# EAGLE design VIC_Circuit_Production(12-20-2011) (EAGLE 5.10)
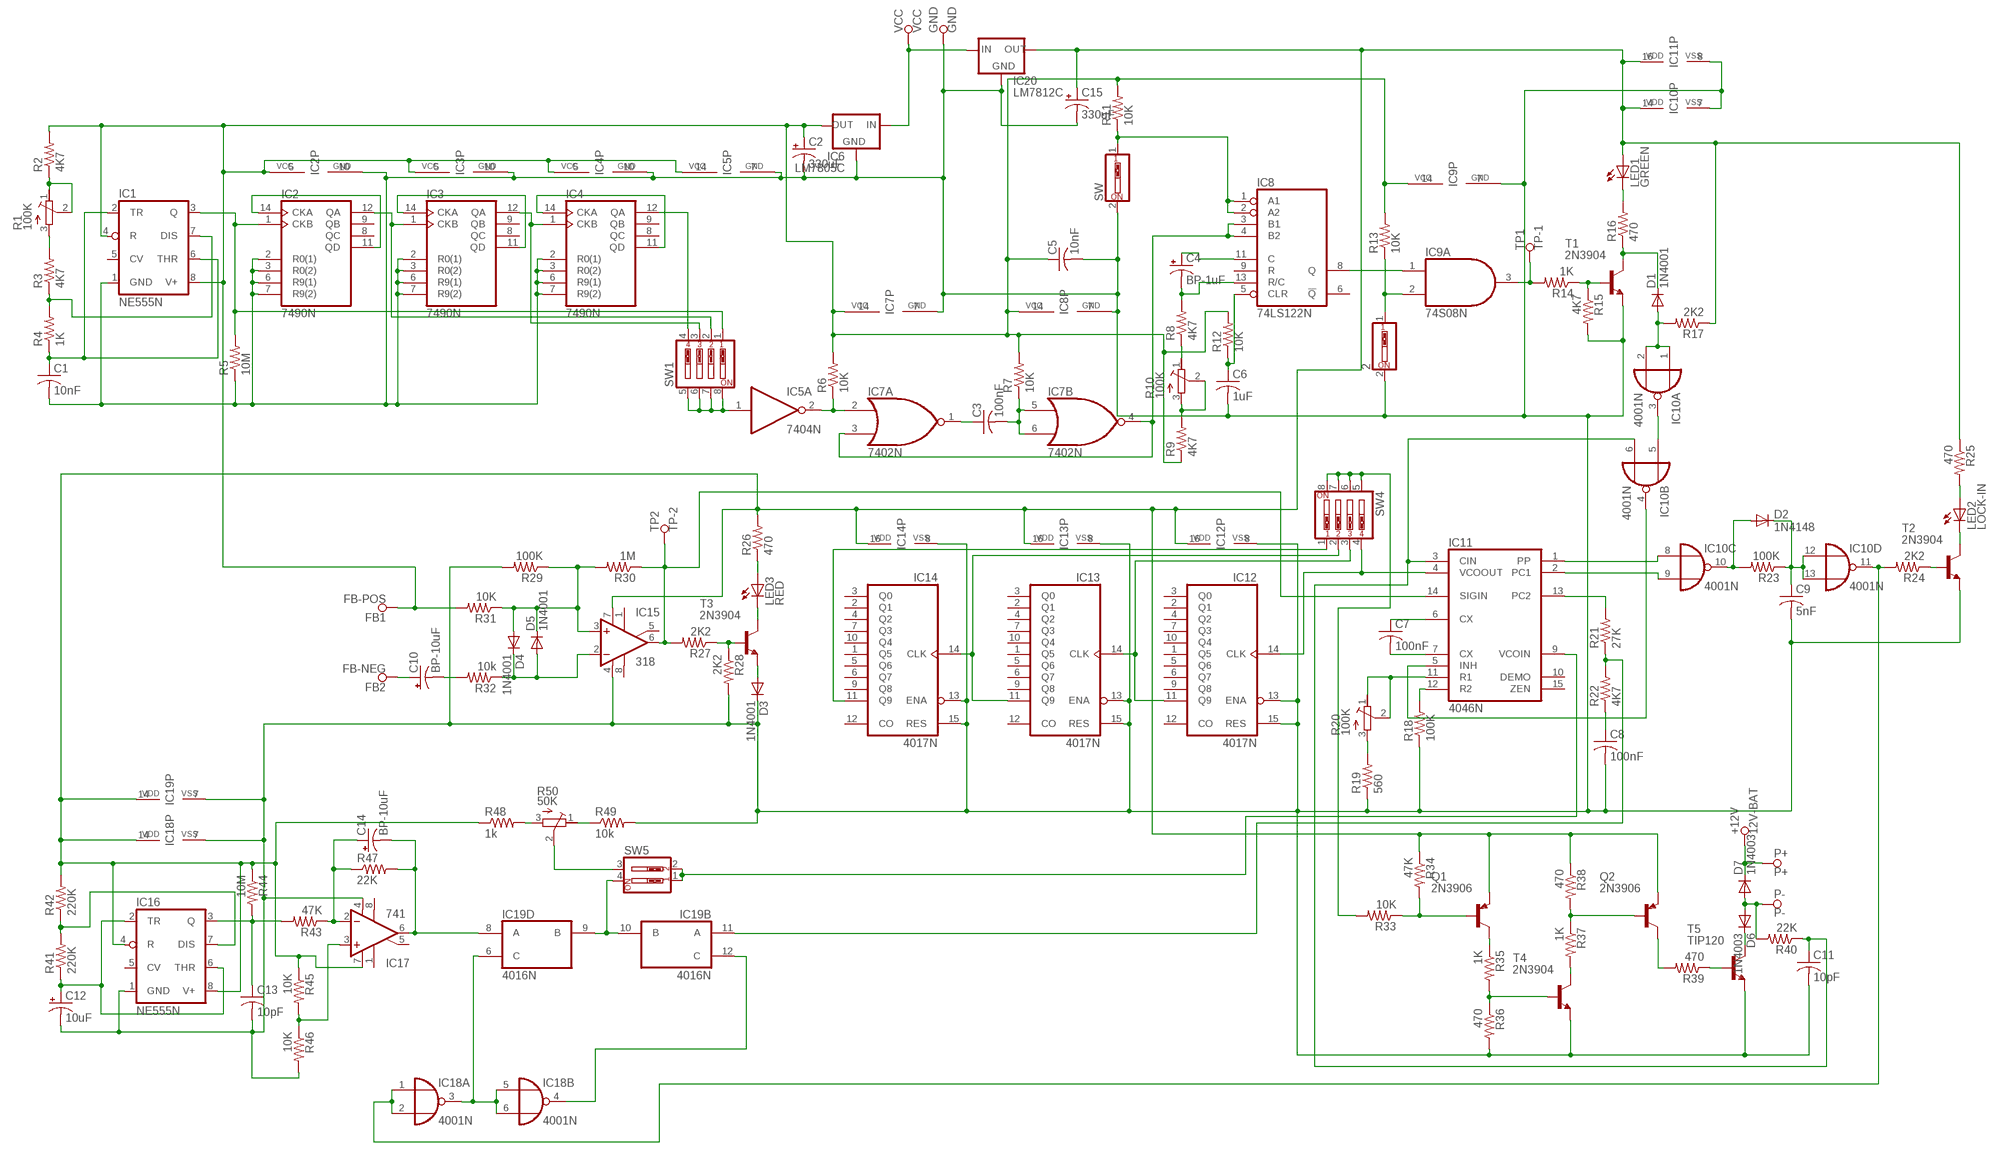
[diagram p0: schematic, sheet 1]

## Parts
2  SW_DIP-1  [EDG-01]
+12V  12V-BAT  SPECIAL_DRILL_0.1250  [PAD_0.1250]
C1  10nF  C-US050-024X044  [C050-024X044]
C2  330uF  CPOL-USE5-10.5  [E5-10,5]
C3  100nF  C-US050-024X044  [C050-024X044]
C4  BP-1uF  CPOL-USE2.5-6  [E2,5-6]
C5  10nF  C-US050-024X044  [C050-024X044]
C6  1uF  C-US050-024X044  [C050-024X044]
C7  100nF  C-US050-024X044  [C050-024X044]
C8  100nF  C-US050-024X044  [C050-024X044]
C9  5nF  C-US050-024X044  [C050-024X044]
C10  BP-10uF  CPOL-USE22-6AXIAL  [E22-6]
C11  10pF  C-US050-024X044  [C050-024X044]
C12  10uF  CPOL-USE2.5-6  [E2,5-6]
C13  10pF  C-US050-024X044  [C050-024X044]
C14  BP-10uF  CPOL-USE22-6AXIAL  [E22-6]
C15  330uF  CPOL-USE5-10.5  [E5-10,5]
D1  1N4001  1N4004  [DO41-10]
D2  1N4148  1N4004  [DO41-10]
D3  1N4001  1N4004  [DO41-10]
D4  1N4001  1N4004  [DO41-10]
D5  1N4001  1N4004  [DO41-10]
D6  1N4003  1N5060GP  [DO15-12]
D7  1N4003  1N4004  [DO41-10]
FB1  FB-POS  SPECIAL_DRILL_0.1250  [PAD_0.1250]
FB2  FB-NEG  SPECIAL_DRILL_0.1250  [PAD_0.1250]
GND  GND  SPECIAL_DRILL_0.1250  [PAD_0.1250]
IC1  NE555N  [DIL08]
IC2  7490N  [DIL14]
IC3  7490N  [DIL14]
IC4  7490N  [DIL14]
IC5  7404N  [DIL14]
IC6  LM7805C  78XXS  [78XXS]
IC7  7402N  [DIL14]
IC8  74LS122N  [DIL14]
IC9  74S08N  [DIL14]
IC10  4001N  [DIL14]
IC11  4046N  [DIL16]
IC12  4017N  [DIL16]
IC13  4017N  [DIL16]
IC14  4017N  [DIL16]
IC15  318  LM741P  [DIL08]
IC16  NE555N  [DIL08]
IC17  741  LM741P  [DIL08]
IC18  4001N  [DIL14]
IC19  4016N  [DIL14]
IC20  LM7812C  78XXS  [78XXS]
LED1  GREEN  LED5MM  [LED5MM]
LED2  LOCK-IN  LED5MM  [LED5MM]
LED3  RED  LED5MM  [LED5MM]
P+  P+  SPECIAL_DRILL_0.1250  [PAD_0.1250]
P-  P-  SPECIAL_DRILL_0.1250  [PAD_0.1250]
Q1  2N3906  [TO92]
Q2  2N3906  [TO92]
R1  100K  R-TRIMMT93YA  [RTRIMT93YA]
R2  4K7  R-US_0207/10  [0207/10]
R3  4K7  R-US_0207/10  [0207/10]
R4  1K  R-US_0207/10  [0207/10]
R5  10M  R-US_0207/10  [0207/10]
R6  10K  R-US_0207/10  [0207/10]
R7  10K  R-US_0207/10  [0207/10]
R8  4K7  R-US_0207/10  [0207/10]
R9  4K7  R-US_0207/10  [0207/10]
R10  100K  R-TRIMMT93YA  [RTRIMT93YA]
R11  10K  R-US_0207/10  [0207/10]
R12  10K  R-US_0207/10  [0207/10]
R13  10K  R-US_0207/10  [0207/10]
R14  1K  R-US_0207/10  [0207/10]
R15  4K7  R-US_0207/10  [0207/10]
R16  470  R-US_0207/10  [0207/10]
R17  2K2  R-US_0207/10  [0207/10]
R18  100K  R-US_0207/10  [0207/10]
R19  560  R-US_0207/10  [0207/10]
R20  100K  R-TRIMMT93YA  [RTRIMT93YA]
R21  27K  R-US_0207/10  [0207/10]
R22  4K7  R-US_0207/10  [0207/10]
R23  100K  R-US_0207/10  [0207/10]
R24  2K2  R-US_0207/10  [0207/10]
R25  470  R-US_0207/10  [0207/10]
R26  470  R-US_0207/10  [0207/10]
R27  2K2  R-US_0207/10  [0207/10]
R28  2K2  R-US_0207/10  [0207/10]
R29  100K  R-US_0207/10  [0207/10]
R30  1M  R-US_0207/10  [0207/10]
R31  10K  R-US_0207/10  [0207/10]
R32  10k  R-US_0207/10  [0207/10]
R33  10K  R-US_0207/10  [0207/10]
R34  47K  R-US_0207/10  [0207/10]
R35  1K  R-US_0207/10  [0207/10]
R36  470  R-US_0207/10  [0207/10]
R37  1K  R-US_0207/10  [0207/10]
R38  470  R-US_0207/10  [0207/10]
R39  470  R-US_0207/10  [0207/10]
R40  22K  R-US_0207/10  [0207/10]
R41  220K  R-US_0207/10  [0207/10]
R42  220K  R-US_0207/10  [0207/10]
R43  47K  R-US_0207/10  [0207/10]
R44  10M  R-US_0207/10  [0207/10]
R45  10K  R-US_0207/10  [0207/10]
R46  10K  R-US_0207/10  [0207/10]
R47  22K  R-US_0207/10  [0207/10]
R48  1k  R-US_0207/10  [0207/10]
R49  10k  R-US_0207/10  [0207/10]
R50  50K  R-TRIMMT93YA  [RTRIMT93YA]
SW  SW_DIP-1  [EDG-01]
SW1  SW_DIP-4  [EDG-04]
SW4  SW_DIP-4  [EDG-04]
SW5  SW_DIP-2  [EDG-02]
T1  2N3904  [TO92]
T2  2N3904  [TO92]
T3  2N3904  [TO92]
T4  2N3904  [TO92]
T5  TIP120  -NPN-TO220V  [TO220V]
TP1  TP-1  SPECIAL_DRILL_0.1000  [PAD_0.1000]
TP2  TP-2  SPECIAL_DRILL_0.1000  [PAD_0.1000]
VCC  VCC  SPECIAL_DRILL_0.1250  [PAD_0.1250]

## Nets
N$1: IC5.1(A:I) SW1.5 SW1.6 SW1.7 SW1.8
N$2: R1.3(E) R3.2
N$3: IC1.7(DIS) R3.1 R4.2
N$4: IC4.12(QA) SW1.4
N$5: C1.1 IC1.2(TR) IC1.6(THR) R4.1
N$6: IC16.7(DIS) R41.2 R42.1
N$7: C15.+ IC10.14(P:VDD) IC11.16(VDD) IC12.16(VDD) IC13.16(VDD) IC14.16(VDD) IC15.7(V+) IC16.4(R) IC16.8(V+) IC17.7(V+) IC18.14(P:VDD) IC19.14(P:VDD) IC20.OUT LED1.A Q1.3(E) Q2.3(E) R17.1 R25.1 R26.2 R34.1 R38.1 R42.2 R44.1 R45.1 R48.1
N$8: 2.2 C1.2 C2.- C5.2 C6.2 C8.2 C9.2 C11.2 C12.- C13.2 C15.- D3.C GND.1 IC1.1(GND) IC2.2(R0(1)) IC2.3(R0(2)) IC2.6(R9(1)) IC2.7(R9(2)) IC2.10(GND) IC3.2(R0(1)) IC3.3(R0(2)) IC3.6(R9(1)) IC3.7(R9(2)) IC3.10(GND) IC4.2(R0(1)) IC4.3(R0(2)) IC4.6(R9(1)) IC4.7(R9(2)) IC4.10(GND) IC5.7(P:GND) IC6.GND IC7.7(P:GND) IC8.7(GND) IC9.7(P:GND) IC10.7(P:VSS) IC11.8(VSS) IC12.8(VSS) IC12.13(ENA) IC12.15(RES) IC13.8(VSS) IC13.13(ENA) IC13.15(RES) IC14.8(VSS) IC14.13(ENA) IC14.15(RES) IC15.4(V-) IC16.1(GND) IC17.4(V-) IC18.7(P:VSS) IC19.7(P:VSS) IC20.GND R5.1 R15.2 R18.1 R19.1 R28.2 R29.2 R36.2 R46.2 R49.2 SW.2 T1.3(E) T2.3(E) T4.3(E) T5.3(E)
N$9: R1.1(A) R1.2(S) R2.1
N$10: IC5.2(A:O) IC7.2(A:I0) R6.1
N$11: IC3.12(QA) IC4.1(CKB) SW1.3
N$12: IC1.3(Q) IC2.1(CKB) R5.2 SW1.1
N$13: C3.2 IC7.5(B:I0) IC7.6(B:I1) R7.1
N$14: IC2.11(QD) IC2.14(CKA)
N$15: IC2.12(QA) IC3.1(CKB) SW1.2
N$16: C3.1 IC7.1(A:O)
N$17: IC3.11(QD) IC3.14(CKA)
N$18: C4.+ IC8.11(C)
N$19: IC7.3(A:I1) IC7.4(B:O) IC8.3(B1) IC8.4(B2)
N$20: IC4.11(QD) IC4.14(CKA)
N$21: R8.1 R10.1(A)
N$22: R9.2 R10.2(S) R10.3(E)
N$23: C4.- IC8.13(R/C) R8.2
N$24: C6.1 IC8.5(CLR) R12.1
N$25: C7.1 IC11.6(CX)
N$26: C7.2 IC11.7(CX)
N$27: IC8.1(A1) IC8.2(A2) R11.1 SW.1
N$28: 2.1 IC9.2(A:I1) R13.1
N$29: IC8.8(Q) IC9.1(A:I0)
N$30: D1.A IC10.1(A:I0) IC10.2(A:I1) R17.2
N$31: IC9.3(A:O) R14.2 TP1.1
N$32: R14.1 R15.1 T1.2(B)
N$33: IC10.3(A:O) IC10.5(B:I0)
N$34: IC11.12(R2) R18.2
N$35: LED1.K(C) R16.2
N$36: D1.C R16.1 T1.1(C)
N$37: C12.+ IC16.2(TR) IC16.6(THR) R41.1
N$38: IC10.4(B:O) IC11.5(INH)
N$39: IC11.11(R1) R20.1(A) R20.2(S)
N$40: R19.2 R20.3(E)
N$41: Q2.2(B) R37.1 R38.2
N$42: IC10.8(C:I0) IC11.1(PP)
N$43: IC11.13(PC2) R21.2
N$44: IC19.11(B:A) R21.1 R22.2
N$45: C8.1 R22.1
N$46: IC10.9(C:I1) IC11.2(PC1)
N$47: D2.A IC10.10(C:O) R23.2
N$48: C9.1 D2.C IC10.12(D:I0) IC10.13(D:I1) R23.1
N$49: IC10.11(D:O) IC18.1(A:I0) IC18.2(A:I1) R24.2
N$50: R24.1 T2.2(B)
N$51: LED2.K(C) T2.1(C)
N$52: LED2.A R25.2
N$53: R37.2 T4.1(C)
N$54: Q1.2(B) R33.1 R34.2
N$55: IC11.4(VCOOUT) IC12.14(CLK) SW4.4
N$56: IC12.11(Q9) IC13.14(CLK) SW4.3
N$57: IC13.11(Q9) IC14.14(CLK) SW4.2
N$58: R33.2 SW4.5 SW4.6 SW4.7 SW4.8
N$59: R35.2 R36.1 T4.2(B)
N$60: IC18.4(B:O) IC19.12(B:C)
N$61: Q2.1(C) R39.2
N$62: R39.1 T5.1(B)
N$63: IC6.IN IC20.IN VCC.1
N$64: IC14.11(Q9) SW4.1
N$65: C10.+ FB2.1
N$66: D6.C T5.2(C)
N$67: IC11.14(SIGIN) IC15.6(OUT) R27.2 R30.1 TP2.1
N$68: R27.1 R28.1 T3.2(B)
N$69: D3.A T3.3(E)
N$70: LED3.K(C) T3.1(C)
N$71: LED3.A R26.1
N$72: D6.A D7.A P-.1 R40.2
N$73: C11.1 IC10.6(B:I1) IC11.3(CIN) R40.1
N$74: C10.- R32.2
N$75: +12V.1 D7.C P+.1
N$76: Q1.1(C) R35.1
N$77: D4.A D5.C IC15.3(+IN) R29.1 R30.2 R31.1
N$78: D4.C D5.A IC15.2(-IN) R32.1
N$81: C2.+ C5.1 FB1.1 IC1.4(R) IC1.8(V+) IC2.5(VCC) IC3.5(VCC) IC4.5(VCC) IC5.14(P:VCC) IC6.OUT IC7.14(P:VCC) IC8.14(VCC) IC9.14(P:VCC) R2.2 R6.2 R7.2 R9.1 R11.2 R12.2 R13.2 R31.2
N$84: C13.1 IC16.3(Q) R43.2 R44.2
N$86: C14.+ IC17.2(-IN) R43.1 R47.1
N$87: C14.- IC17.6(OUT) IC19.8(D:A) R47.2
N$89: IC17.3(+IN) R45.2 R46.1
N$94: IC18.3(A:O) IC18.5(B:I0) IC18.6(B:I1) IC19.6(D:C)
N$95: IC19.9(D:B) IC19.10(B:B) SW5.4
N$97: IC11.9(VCOIN) SW5.1 SW5.2
N$98: R48.2 R50.3(E)
N$99: R49.1 R50.1(A)
N$100: R50.2(S) SW5.3
Unconnected: IC1.5(CV) IC2.8(QC) IC2.9(QB) IC3.8(QC) IC3.9(QB) IC4.8(QC) IC4.9(QB) IC5.3(B:I) IC5.4(B:O) IC5.5(C:I) IC5.6(C:O) IC5.8(D:O) IC5.9(D:I) IC5.10(E:O) IC5.11(E:I) IC5.12(F:O) IC5.13(F:I) IC7.8(C:I0) IC7.9(C:I1) IC7.10(C:O) IC7.11(D:I0) IC7.12(D:I1) IC7.13(D:O) IC8.6(!Q) IC8.9(R) IC9.4(B:I0) IC9.5(B:I1) IC9.6(B:O) IC9.8(C:O) IC9.9(C:I0) IC9.10(C:I1) IC9.11(D:O) IC9.12(D:I0) IC9.13(D:I1) IC11.10(DEMO) IC11.15(ZEN) IC12.1(Q5) IC12.2(Q1) IC12.3(Q0) IC12.4(Q2) IC12.5(Q6) IC12.6(Q7) IC12.7(Q3) IC12.9(Q8) IC12.10(Q4) IC12.12(CO) IC13.1(Q5) IC13.2(Q1) IC13.3(Q0) IC13.4(Q2) IC13.5(Q6) IC13.6(Q7) IC13.7(Q3) IC13.9(Q8) IC13.10(Q4) IC13.12(CO) IC14.1(Q5) IC14.2(Q1) IC14.3(Q0) IC14.4(Q2) IC14.5(Q6) IC14.6(Q7) IC14.7(Q3) IC14.9(Q8) IC14.10(Q4) IC14.12(CO) IC15.1(ON1) IC15.5(ON2) IC15.8(OPT) IC16.5(CV) IC17.1(ON1) IC17.5(ON2) IC17.8(OPT) IC18.8(C:I0) IC18.9(C:I1) IC18.10(C:O) IC18.11(D:O) IC18.12(D:I0) IC18.13(D:I1) IC19.1(A:A) IC19.2(A:B) IC19.3(C:B) IC19.4(C:A) IC19.5(C:C) IC19.13(A:C)

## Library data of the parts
2 SW = special:SW_DIP-1: DIP SWITCH
+12V FB1 FB2 GND P+ P- TP1 TP2 VCC = special-drill:SPECIAL_DRILL_: Special drills
C1 C3 C5-C9 C11 C13 = rcl:C-US: CAPACITOR, American symbol
C2 C4 C10 C12 C14 C15 = resistor:CPOL-US: POLARIZED CAPACITOR, American symbol
D1-D5 D7 = diode:1N4004: DIODE
D6 = diode:1N5060GP: DIODE
IC1 IC16 = linear:*555: TIMER
IC2-IC4 = 74xx-us:74*90: Decade, divide by twelve and binary COUNTER
IC5 = 74xx-us:74*04: Hex INVERTER
IC6 IC20 = v-reg:78XXS: VOLTAGE REGULATOR
IC7 = 74xx-us:74*02: Quad 2-input NOR gate
IC8 = 74xx-us:74*122: Retriggerable monostable MULTIVIBRATOR
IC9 = 74xx-us:74*08: Quad 2-input AND gate
IC10 IC18 = 40xx:4001: Quad 2-input NOR
IC11 = 40xx:4046: Micropower PLL
IC12-IC14 = 40xx:4017: COUNTER/DIVIDER
IC15 IC17 = linear:*741: OP AMP
IC19 = 40xx:4016: Quad bilateral ANALOG SWITCH
LED1-LED3 = led:LED: LED
Q1 Q2 = transistor-pnp:2N3906: PNP Transistor
R1 R10 R20 R50 = rcl:R-TRIMM: Trimm resistor
R2-R9 R11-R19 R21-R49 = resistor:R-US_: RESISTOR, American symbol
SW1 SW4 = special:SW_DIP-4: DIP SWITCH
SW5 = special:SW_DIP-2: DIP SWITCH
T1-T4 = transistor:2N3904: NPN TRANSISTOR
T5 = transistor:*-NPN-: NPN Transistror BF959 corrected 2008.03.06

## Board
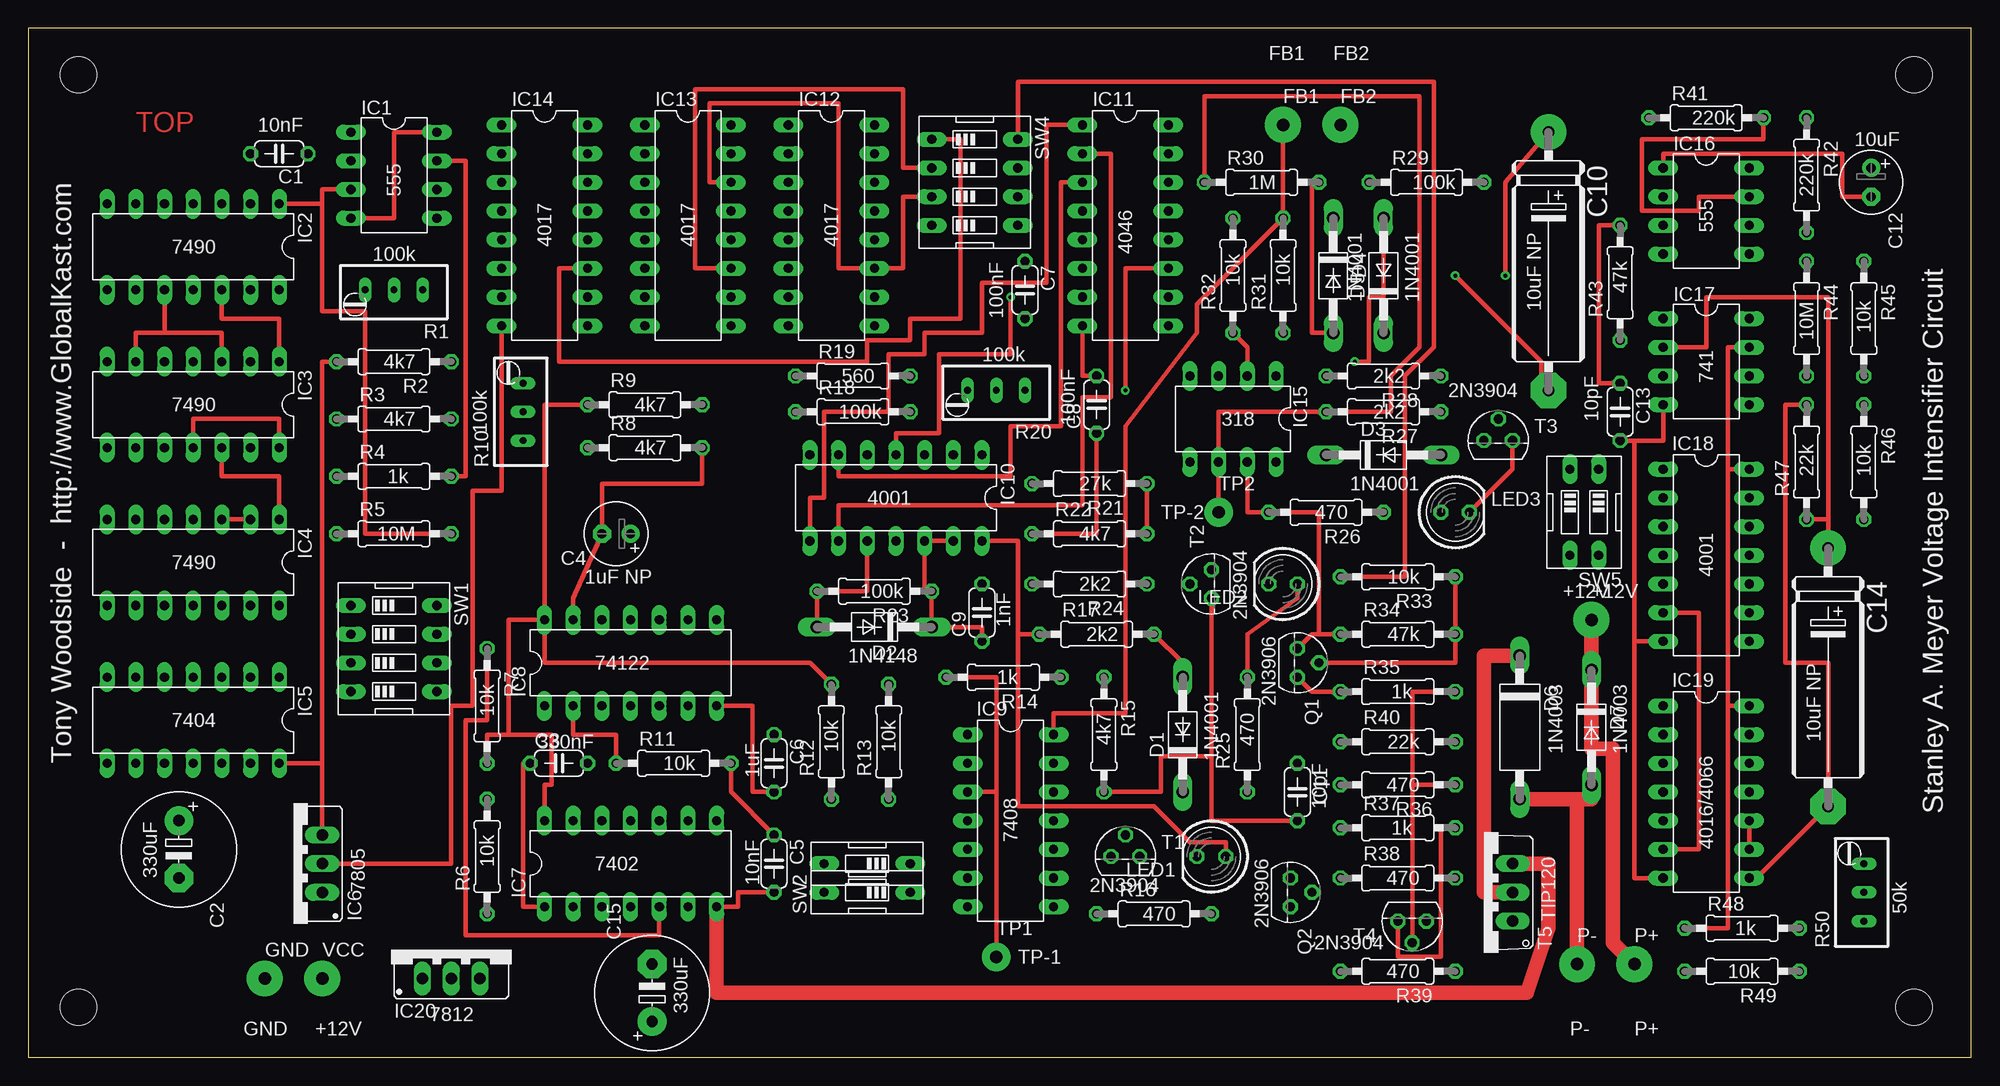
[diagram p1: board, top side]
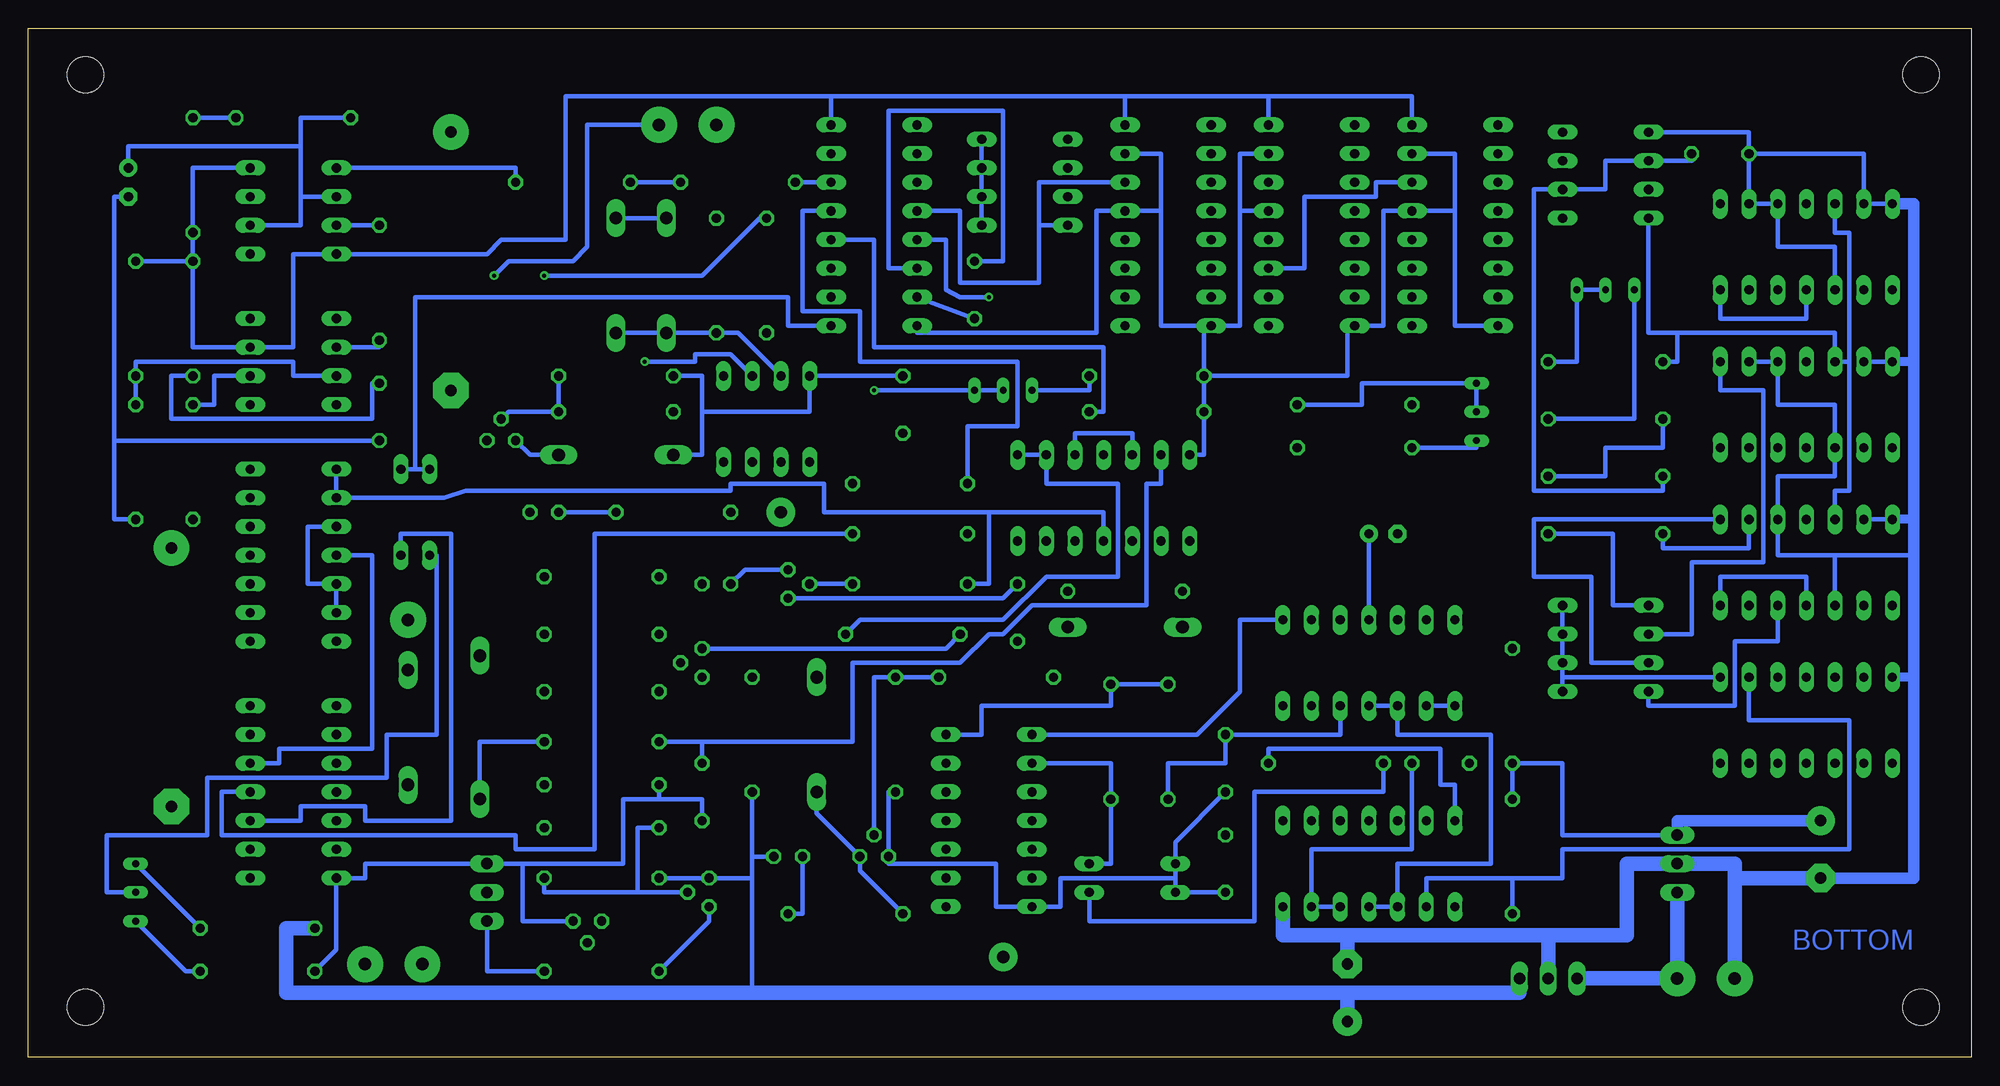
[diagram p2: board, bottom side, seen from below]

Size 172.06 x 91.11 mm. Coordinates in mm from the lower left corner, seen from the top.
Outline: 0,0 172.06,0 172.06,91.11 0,91.11 0,0
Copper layers (1*16): Top 0.0356mm / dielectric 1.5011mm / Bottom 0.0356mm
Design rules "SilverCircuits": minimum track width 7mil, minimum drill 14mil, track to track 7mil, track to pad 7mil, pad to pad 7mil, via to via 7mil, smd to smd 0mil, copper to edge 20mil, drill to drill 8mil, minimum pad ring 10mil, minimum via ring 8mil, stop-mask expansion 4mil, vias tented up to drill 0mil, thermal gap 10mil
Holes 3.2 mm at 4.44,4.45 167,4.45 167,87 4.44,87

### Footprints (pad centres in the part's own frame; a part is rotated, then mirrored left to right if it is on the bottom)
EDG-01 = drill 0.813 long: 1 0,-3.81; 2 0,3.81
PAD_0.1250 = drill 1.1 pad 3.175 round: 1 0,0
C050-024X044 = drill 0.813 octagon: 1 -2.54,0; 2 2.54,0
E5-10,5 = drill 1.016 pad 2.54 round: + -2.54,0 | drill 1.016 pad 2.54 octagon: - 2.54,0
E2,5-6 = drill 0.813 pad 1.6 round: + -1.27,0 | drill 0.813 pad 1.6 octagon: - 1.27,0
E22-6 = drill 1.016 pad 3.15 round: + -11.43,0 | drill 1.016 pad 3.15 octagon: - 11.43,0
DO41-10 = drill 1.118 long: A 5.08,0; C -5.08,0
DO15-12 = drill 1.118 long: A 6.35,0; C -6.35,0
DIL08 = drill 0.813 pad 1.27 long: 1 -3.81,-3.81; 2 -1.27,-3.81; 3 1.27,-3.81; 4 3.81,-3.81; 5 3.81,3.81; 6 1.27,3.81; 7 -1.27,3.81; 8 -3.81,3.81
DIL14 = drill 0.813 long: 1 -7.62,-3.81; 2 -5.08,-3.81; 3 -2.54,-3.81; 4 0,-3.81; 5 2.54,-3.81; 6 5.08,-3.81; 7 7.62,-3.81; 8 7.62,3.81; 9 5.08,3.81; 10 2.54,3.81; 11 0,3.81; 12 -2.54,3.81; 13 -5.08,3.81; 14 -7.62,3.81
78XXS = drill 1.016 long: GND 0,-2.54; IN -2.54,-2.54; OUT 2.54,-2.54
DIL16 = drill 0.813 long: 1 -8.89,-3.81; 2 -6.35,-3.81; 3 -3.81,-3.81; 4 -1.27,-3.81; 5 1.27,-3.81; 6 3.81,-3.81; 7 6.35,-3.81; 8 8.89,-3.81; 9 8.89,3.81; 10 6.35,3.81; 11 3.81,3.81; 12 1.27,3.81; 13 -1.27,3.81; 14 -3.81,3.81; 15 -6.35,3.81; 16 -8.89,3.81
LED5MM = drill 0.813 octagon: A -1.27,0; K 1.27,0
TO92 = drill 0.813 octagon: 1 1.27,0; 2 0,1.905; 3 -1.27,0
RTRIMT93YA = drill 0.61 long: 1 0,-2.54; 2 0,0; 3 0,2.54
0207/10 = drill 0.813 octagon: 1 -5.08,0; 2 5.08,0
EDG-04 = drill 0.813 long: 1 -3.81,-3.81; 2 -1.27,-3.81; 3 1.27,-3.81; 4 3.81,-3.81; 5 3.81,3.81; 6 1.27,3.81; 7 -1.27,3.81; 8 -3.81,3.81
EDG-02 = drill 0.813 long: 1 -1.27,-3.81; 2 1.27,-3.81; 3 1.27,3.81; 4 -1.27,3.81
TO220V = drill 1.016 long: 1 -2.54,-2.54; 2 0,-2.54; 3 2.54,-2.54
PAD_0.1000 = drill 1.1 pad 2.54 round: 1 0,0

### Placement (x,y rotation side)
2  74.3,17.14 90 top
+12V  138.43,38.73 0 top
C1  22.23,80.01 180 top
C2  13.33,18.41 270 top
C3  46.99,26.04 0 top
C4  52.07,46.35 180 top
C5  66.04,17.14 270 top
C6  66.04,26.04 270 top
C7  88.27,67.94 270 top
C8  94.62,57.78 90 top
C9  84.45,39.37 90 top
C10  134.62,70.49 270 top
C11  112.4,23.5 270 top
C12  163.19,77.47 270 top
C13  140.97,57.15 270 top
C14  159.38,33.66 270 top
C15  55.24,5.71 90 top
D1  102.23,28.58 90 top
D2  74.93,38.1 180 top
D3  120.02,53.34 0 top
D4  115.57,69.22 270 top
D5  120.02,69.22 90 top
D6  132.08,29.21 270 top
D7  138.43,29.21 270 top
FB1  111.12,82.55 0 top
FB2  116.2,82.55 0 top
GND  20.95,6.98 0 top
IC1  32.38,78.1 270 top
IC2  14.6,71.75 180 top
IC3  14.6,57.78 180 top
IC4  14.6,43.81 180 top
IC5  14.6,29.84 180 top
IC6  23.49,17.14 90 top
IC7  53.34,17.14 0 top
IC8  53.34,34.92 0 top
IC9  87,20.95 270 top
IC10  76.84,49.53 180 top
IC11  97.16,73.66 270 top
IC12  71.12,73.66 270 top
IC13  58.42,73.66 270 top
IC14  45.72,73.66 270 top
IC15  106.68,56.52 180 top
IC16  148.59,74.93 270 top
IC17  148.59,61.6 270 top
IC18  148.59,44.45 270 top
IC19  148.59,23.5 270 top
IC20  37.46,9.53 0 top
LED1  104.78,17.78 180 top
LED2  111.12,41.91 180 top
LED3  126.37,48.26 0 top
P+  142.24,8.25 0 top
P-  137.16,8.25 0 top
Q1  112.4,34.92 270 top
Q2  111.76,14.61 270 top
R1  32.38,67.94 90 top
R2  32.38,61.6 180 top
R3  32.38,56.52 0 top
R4  32.38,51.44 0 top
R5  32.38,46.35 0 top
R6  40.64,17.78 90 top
R7  40.64,31.12 270 top
R8  54.61,53.98 0 top
R9  54.61,57.78 0 top
R10  43.81,57.15 0 top
R11  57.15,26.04 0 top
R12  71.12,27.94 90 top
R13  76.2,27.94 90 top
R14  86.36,33.66 180 top
R15  95.25,28.58 270 top
R16  99.7,12.7 0 top
R17  94.62,37.46 0 top
R18  73.03,57.15 0 top
R19  73.03,60.32 0 top
R20  85.73,59.05 90 top
R21  93.98,50.8 180 top
R22  93.98,46.35 0 top
R23  74.93,41.27 180 top
R24  93.98,41.91 180 top
R25  107.95,28.58 90 top
R26  114.94,48.26 180 top
R27  120.02,57.15 180 top
R28  120.02,60.32 180 top
R29  123.83,77.47 0 top
R30  109.22,77.47 0 top
R31  111.12,69.22 90 top
R32  106.68,69.22 90 top
R33  121.28,42.55 180 top
R34  121.28,37.46 0 top
R35  121.28,32.38 0 top
R36  121.28,24.13 180 top
R37  121.28,20.32 0 top
R38  121.28,15.88 0 top
R39  121.28,7.62 180 top
R40  121.28,27.94 0 top
R41  148.59,83.19 0 top
R42  157.48,78.1 270 top
R43  140.97,68.58 90 top
R44  157.48,65.41 270 top
R45  162.56,65.41 270 top
R46  162.56,52.7 270 top
R47  157.48,52.7 90 top
R48  151.77,11.43 0 top
R49  151.77,7.62 180 top
R50  162.56,14.61 0 top
SW  74.3,14.61 90 top
SW1  32.38,36.2 270 top
SW4  83.82,77.47 270 top
SW5  137.8,48.26 180 top
T1  97.16,17.78 0 top
T2  104.78,41.91 90 top
T3  130.18,54.61 0 top
T4  122.56,12.07 180 top
T5  128.91,14.61 90 top
TP1  85.73,8.89 0 top
TP2  105.41,48.26 0 top
VCC  26.03,6.98 0 top

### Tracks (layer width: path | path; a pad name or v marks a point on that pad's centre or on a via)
N$1
  Bottom 0.406: SW1.8 SW1.7 SW1.6 36.2,33.66 | IC5.1 36.2,33.66 | 36.2,33.66 SW1.5
N$2
  Bottom 0.406: R1.3 29.84,56.52 R3.2
N$3
  Top 0.406: IC1.7 38.73,79.38 38.73,51.44 R4.2
  Bottom 0.406: R3.1 27.3,53.98 32.38,53.98 32.38,51.44 R4.2
N$4
  Bottom 0.406: IC4.12 17.14,36.83 20.95,36.83 20.95,31.12 28.57,31.12 SW1.4
N$5
  Bottom 0.406: C1.1 24.77,79.38 IC1.2 32.38,79.38 32.38,76.84 IC1.6 38.73,76.84 38.73,50.16 27.3,50.16 R4.1
N$6
  Top 0.406: IC16.7 147.96,76.2 147.96,74.93 142.88,74.93 142.88,81.28 153.67,81.28 R41.2
  Bottom 0.406: R41.2 R42.1
N$7
  Top 0.406: IC10.14 87.63,45.72 87.63,37.46 | 87.63,37.46 R17.1 | IC15.7 107.95,48.26 R26.2 114.3,48.26 114.3,37.46 | 114.3,37.46 R34.1 | 150.5,31.12 150.5,11.43 R48.1 | 150.5,31.12 IC19.14 | 150.5,31.12 150.5,52.07 | 150.5,52.07 IC18.14 | 150.5,52.07 150.5,62.87 IC17.7 | 87.63,37.46 87.63,22.23 99.7,22.23 102.87,19.05 106.05,19.05 LED1.A | Q1.3 113.67,37.46 114.3,37.46
  Bottom 0.406: R38.1 Q2.3 107.95,15.88 | 107.95,5.71 107.95,15.88 | 107.95,15.88 107.95,17.78 | 107.95,17.78 R25.1 | R17.1 90.81,36.2 Q1.3 | 62.23,85.09 49.53,85.09 IC14.16 | 62.23,85.09 IC13.16 | 74.93,85.09 62.23,85.09 | 74.93,85.09 IC12.16 | 100.97,85.09 74.93,85.09 | R44.1 157.48,62.87 IC17.7 148.59,62.87 148.59,71.12 IC16.4 131.44,71.12 130.18,72.39 124.46,72.39 124.46,85.09 100.97,85.09 | R44.1 R45.1 | R44.1 R42.2 157.48,78.74 IC16.8 | 100.97,85.09 IC11.16 | 107.95,17.78 LED1.A
  Bottom 1.27: R48.1 149.22,11.43 149.22,5.71 107.95,5.71 55.24,5.71 | IC20.OUT 40,5.71 55.24,5.71 | 55.24,5.71 C15.+
N$8
  Top 0.406: 12.06,64.13 17.14,64.13 IC3.3 | 12.06,64.13 IC2.10 | IC4.3 IC4.2 | IC7.7 62.87,13.34 62.87,14.61 C5.2 | IC8.7 64.14,31.12 64.14,23.5 C6.2 | 142.24,54.61 144.78,54.61 IC17.4 | 142.24,36.83 142.24,54.61 | 142.24,54.61 C13.2 | C11.2 104.78,20.95 104.78,26.67 | 142.24,36.83 142.24,15.88 IC19.7 | 142.24,36.83 IC18.7 | C8.2 93.34,60.32 IC11.8 | IC6.GND 37.46,17.14 37.46,31.12 39.37,31.12 39.37,50.16 41.91,50.16 IC14.8 | 104.78,26.67 T2.3 | 104.78,26.67 100.33,26.67 100.33,23.5 R15.2 | IC16.1 144.78,80.01 160.66,80.01 160.66,76.2 C12.- | 12.06,64.13 9.53,64.13 IC3.6
  Top 1.27: T5.3 134.62,17.14 134.62,11.43 132.72,5.71 60.96,5.71 IC7.7
  Bottom 0.406: IC3.2 IC3.3 17.14,57.78 12.06,57.78 IC3.10 12.06,51.44 17.14,51.44 IC4.3 17.14,44.45 12.06,44.45 | IC2.10 12.06,71.75 17.14,71.75 IC2.3 IC2.2 C1.2 | R5.1 27.3,45.09 19.69,45.09 IC4.2 | IC2.7 IC2.6 9.53,80.01 C1.2 | IC4.7 IC4.6 | IC3.7 IC3.6 | 12.06,44.45 IC4.10 | 5.08,44.45 12.06,44.45 | C5.2 SW.2 70.48,15.88 | R15.2 95.89,23.5 T1.3 95.89,17.14 86.36,17.14 86.36,13.34 IC9.7 80.65,13.34 80.65,15.88 70.48,15.88 | 70.48,15.88 2.2 70.48,19.05 C6.2 | C13.2 164.47,54.61 | C12.- 164.47,76.2 164.47,54.61 | 164.47,54.61 164.47,47.62 R46.2 | T2.3 85.73,40.64 C9.2 | 116.2,22.86 112.4,22.86 C11.2 | T4.3 128.27,12.07 128.27,17.14 | 116.2,22.86 119.38,22.86 119.38,17.14 128.27,17.14 | 116.2,22.86 R36.2 | 128.27,17.14 T5.3 142.24,17.14 142.24,15.88 IC19.7 144.78,9.53 R49.2 | 112.4,57.15 112.4,60.32 R28.2 | 112.4,57.15 112.4,53.34 D3.C | C8.2 IC15.4 102.87,57.15 112.4,57.15 | 71.76,74.93 71.76,80.01 IC12.15 | 64.77,74.93 64.77,80.01 IC13.15 | R19.1 R18.1 67.95,53.34 IC10.7 | R19.1 67.95,64.77 IC12.8 | 64.77,74.93 64.77,64.77 IC12.8 | 64.77,74.93 IC13.13 | 71.76,74.93 71.76,64.77 IC12.8 | 71.76,74.93 IC12.13 77.47,74.93 77.47,64.13 93.34,64.13 IC11.8 | IC1.1 19.69,81.91 C1.2 | 45.72,74.93 45.72,64.77 IC14.8 | 45.72,74.93 IC14.13 52.07,74.93 52.07,64.77 IC13.8 55.24,64.77 55.24,60.32 R19.1 | 45.72,74.93 45.72,80.01 IC14.15 | R29.2 128.91,78.74 IC16.1
  Bottom 0.813: 5.08,47.62 IC4.7 | 5.08,33.66 IC5.7 | 5.08,61.6 IC3.7
  Bottom 1.016: IC2.7 5.08,75.56 5.08,61.6 5.08,47.62 5.08,44.45 5.08,33.66 5.08,15.88 C2.-
  Bottom 1.27: 20.95,15.88 GND.1 | 20.95,15.88 20.95,17.14 IC6.GND 30.48,17.14 30.48,10.79 37.46,10.79 | C2.- 20.95,15.88 | IC7.7 60.96,10.79 55.24,10.79 | 37.46,10.79 55.24,10.79 | 37.46,10.79 IC20.GND | 55.24,10.79 C15.-
N$9
  Bottom 0.406: R1.2 R1.1 34.92,61.6 R2.1
N$10
  Bottom 0.406: IC5.2 19.69,29.84 10.79,29.84 10.79,18.41 36.2,18.41 36.2,15.88 40.64,15.88 | 40.64,15.88 48.26,15.88 IC7.2 | 40.64,15.88 R6.1
N$11
  Top 0.406: IC3.12 17.14,51.44 22.23,51.44 IC4.1
  Bottom 0.406: SW1.3 33.65,34.92 33.65,42.55 38.73,42.55 38.73,47.62 IC4.1
N$12
  Top 0.406: R5.2 29.84,46.35 29.84,66.04 26.03,66.04 26.03,75.56 | 26.03,75.56 IC2.1 | 26.03,75.56 26.03,76.84 IC1.3
  Bottom 0.406: SW1.1 31.75,40.01 31.75,46.35 R5.2
N$13
  Top 0.406: IC7.5 55.88,10.79 38.73,10.79 38.73,29.84 40.64,29.84 R7.1
  Bottom 0.406: IC7.5 IC7.6 58.42,18.41 49.53,18.41 C3.2
N$14
  Bottom 0.406: IC2.11 14.6,65.41 22.23,65.41 IC2.14
N$15
  Top 0.406: IC2.12 17.14,65.41 22.23,65.41 IC3.1
  Bottom 0.406: SW1.2 24.77,37.46 24.77,43.81 18.41,43.81 18.41,59.05 22.23,59.05 IC3.1
N$16
  Top 0.406: IC7.1 43.81,13.34 43.81,26.04 C3.1
N$17
  Top 0.406: IC3.11 14.6,56.52 22.23,56.52 IC3.14
N$18
  Bottom 0.406: IC8.11 C4.+
N$19
  Bottom 0.406: IC7.4 IC7.3 50.8,17.14 42.54,17.14 42.54,28.58 50.8,28.58 IC8.3 IC8.4
N$20
  Bottom 0.406: IC4.11 14.6,42.55 22.23,42.55 IC4.14
N$21
  Bottom 0.406: R8.1 43.81,53.98 R10.1
N$22
  Bottom 0.406: R9.2 53.97,57.78 53.97,59.69 R10.3 R10.2
N$23
  Top 0.406: IC8.13 48.26,40.64 C4.- 50.8,50.8 59.69,50.8 R8.2
N$24
  Bottom 0.406: IC8.5 55.88,28.58 C6.1 66.04,26.04 71.12,26.04 R12.1
N$25
  Bottom 0.406: IC11.6 95.89,69.85 95.89,83.82 85.73,83.82 85.73,70.49 C7.1
N$26
  Bottom 0.406: C7.2 IC11.7
N$27
  Top 0.406: R11.1 52.07,28.58 48.26,28.58 IC8.2
  Bottom 0.406: IC8.2 IC8.1 | SW.1 78.11,12.07 63.5,12.07 63.5,23.5 52.07,23.5 R11.1
N$28
  Bottom 0.406: 2.1 76.2,17.14 R13.1 76.2,26.04 IC9.2
N$29
  Bottom 0.406: IC9.1 68.58,28.58 64.77,32.38 64.77,38.73 IC8.8
N$30
  Top 0.406: R17.2 102.23,34.92 D1.A
  Bottom 0.406: IC10.1 IC10.2 81.92,50.8 75.56,50.8 75.56,42.55 81.92,42.55 85.73,38.73 98.43,38.73 R17.2
N$31
  Top 0.406: 85.73,23.5 IC9.3 | TP1.1 85.73,23.5 | R14.2 85.73,33.66 85.73,23.5
N$32
  Bottom 0.406: R14.1 R15.1 97.16,33.66 T1.2
N$33
  Bottom 0.406: IC10.5 74.3,55.24 79.38,55.24 IC10.3
N$34
  Bottom 0.406: R18.2 76.84,57.15 76.84,62.87 97.16,62.87 97.16,72.39 IC11.12
N$35
  Bottom 0.406: LED1.K 103.51,12.7 R16.2
N$36
  Bottom 0.406: D1.C 102.23,21.59 T1.1 98.43,16.51 R16.1
N$37
  Bottom 0.406: 147.96,80.65 147.96,83.19 R41.1 | 147.96,80.65 163.19,80.65 C12.+ | 147.96,76.2 147.96,73.66 IC16.6 | 147.96,76.2 IC16.2 | 147.96,80.65 147.96,76.2
N$38  (via drill 0.36)
  Top 0.406: v87,67.31 87,62.23 80.65,62.23 80.65,55.24 76.84,55.24 IC10.4
  Bottom 0.406: IC11.5 90.81,72.39 90.81,67.94 89.54,67.31 v87,67.31
N$39  (via drill 0.36)
  Top 0.406: IC11.11 97.16,69.85 v97.16,59.05
  Bottom 0.406: R20.2 R20.1 v97.16,59.05
N$40
  Bottom 0.406: R20.3 78.11,59.05 R19.2
N$41
  Bottom 0.178: Q2.2 118.11,14.61
  Bottom 0.406: 118.11,14.61 118.11,20.32 R37.1 | R38.2 126.37,14.61 Q2.2
N$42
  Top 0.406: IC11.1 90.17,82.55 90.17,68.58 84.45,68.58 84.45,64.13 79.38,64.13 79.38,62.23 76.2,62.23 76.2,57.15 70.48,57.15 70.48,49.53 69.22,49.53 IC10.8
N$43
  Bottom 0.406: IC11.13 103.51,74.93 103.51,66.04 98.43,66.04 98.43,61.6 84.45,61.6 84.45,55.88 88.9,55.88 R21.2
N$44
  Top 0.406: R22.2 R21.1
  Bottom 0.406: R22.2 121.92,46.35 121.92,18.41 128.91,18.41 128.91,19.68 154.94,19.68 154.94,23.5 IC19.11
N$45
  Top 0.406: C8.1 94.62,46.35 R22.1
N$46
  Top 0.406: IC11.2 95.89,80.01 95.89,58.42 93.34,58.42 93.34,48.9 71.76,48.9 IC10.9
N$47
  Top 0.406: D2.A R23.2 74.3,41.27 IC10.10
N$48
  Top 0.406: IC10.13 IC10.12 79.38,41.27 R23.1 D2.C 84.45,38.1 C9.1
N$49
  Bottom 0.406: 87,48.26 76.84,48.26 IC10.11 | 87,48.26 101.6,48.26 101.6,50.8 109.86,50.8 109.86,50.16 133.35,50.16 135.25,49.53 IC18.2 IC18.1 | R24.2 87,41.91 87,48.26
N$50
  Bottom 0.406: R24.1 T2.2
N$51
  Bottom 0.406: T2.1 108.59,43.18 LED2.K
N$52
  Top 0.406: R25.2 107.95,37.46 112.4,40.64 LED2.A
N$53
  Top 0.406: T4.1 121.28,8.89 125.09,8.89 125.09,20.32 R37.2
N$54
  Top 0.406: 113.67,34.92 Q1.2 126.37,34.92 R34.2 R33.1
N$55
  Bottom 0.406: 82.55,73.66 82.55,77.47 IC12.14 | IC11.4 89.54,74.93 89.54,68.58 82.55,68.58 82.55,73.66 | 82.55,73.66 SW4.4
N$56
  Top 0.406: IC13.14 60.32,77.47 60.32,84.46 71.76,84.46 71.76,69.85 IC12.11 77.47,69.85 77.47,76.2 SW4.3
N$57
  Top 0.406: SW4.2 77.47,78.74 77.47,85.72 59.05,85.72 59.05,69.85 IC13.11
  Bottom 0.406: IC14.14 52.7,77.47 52.7,76.2 59.05,76.2 59.05,69.85 IC13.11
N$58  (via drill 0.7)
  Top 0.406: SW4.8 87.63,86.36 124.46,86.36 124.46,62.87 121.92,60.32 121.92,42.55 R33.2
  Bottom 0.406: SW4.5 SW4.6 SW4.7 SW4.8
  other vias: 116.2,42.55
N$59
  Top 0.406: 122.56,24.13 R36.1 | T4.2 122.56,24.13 | R35.2 122.56,32.38 122.56,24.13
N$60
  Bottom 0.406: IC19.12 149.86,26.04 149.86,27.3 141.61,27.3 141.61,44.45 IC18.4
N$61
  Bottom 0.406: Q2.1 111.76,12.07 R39.2
N$62
  Bottom 0.406: R39.1 131.44,7.62 T5.1
N$63
  Bottom 1.27: IC6.IN VCC.1 IC20.IN
N$64
  Top 0.406: IC14.11 46.99,69.85 46.99,61.6 74.3,61.6 74.3,63.5 78.11,63.5 78.11,65.41 82.55,65.41 82.55,81.28 SW4.1
N$65  (via drill 0.36)
  Top 0.406: v130.81,69.22 130.81,77.47 C10.+
  Bottom 0.406: v130.81,69.22 129.54,70.49 123.83,70.49 122.56,71.75 122.56,82.55 FB2.1
N$66
  Top 1.27: D6.C 128.91,35.56 128.91,14.61 T5.2
N$67
  Top 0.406: TP2.1 IC15.6 105.41,57.15 R27.2 120.65,57.15 120.65,60.32 123.19,62.87 123.19,85.09 104.14,85.09 R30.1
  Bottom 0.406: R30.1 IC11.14
N$68
  Bottom 0.406: R28.1 R27.1 129.54,57.15 T3.2
N$69
  Bottom 0.406: T3.3 127.63,53.34 D3.A
N$70
  Top 0.406: LED3.K 131.44,52.07 T3.1
N$71
  Bottom 0.406: R26.1 LED3.A
N$72
  Top 1.27: P-.1 137.16,22.86 | 137.16,22.86 138.43,22.86 D7.A | 137.16,22.86 D6.A
  Bottom 0.406: D6.A 132.08,27.94 R40.2
N$73
  Top 0.406: IC11.3 91.44,77.47 91.44,55.88 87,55.88 87,51.44 71.76,51.44 IC10.6
  Bottom 0.406: 112.4,27.94 R40.1 | 112.4,27.94 99.06,27.94 99.06,34.92 89.54,34.92 87,37.46 85.73,37.46 83.19,40.01 73.03,40.01 73.03,50.8 71.76,50.8 IC10.6 | 112.4,27.94 C11.1
N$74  (via drill 0.36)
  Top 0.406: v126.37,69.22 133.99,61.6 133.99,59.05 C10.-
  Bottom 0.406: v126.37,69.22 112.4,69.22 107.31,74.29 R32.2
N$75
  Top 1.27: P+.1 140.34,10.16 140.34,27.3 138.43,27.3 D7.C +12V.1
N$76
  Top 0.406: Q1.1 113.67,32.38 R35.1
N$77
  Top 0.406: D4.A 113.67,64.13 113.67,77.47 R30.2
  Bottom 0.406: IC15.3 109.22,64.13 R31.1 D4.A D5.C | R30.2 R29.1
N$78  (via drill 0.36)
  Top 0.406: v117.48,61.6 118.75,61.6 118.75,67.31 120.02,67.31 D5.A | R32.1 107.95,62.87 IC15.2
  Bottom 0.406: D5.A D4.C | IC15.2 109.86,62.23 113.03,62.23 113.03,61.6 v117.48,61.6
N$81
  Top 0.406: IC6.OUT 26.03,26.04 | 26.03,26.04 IC5.14 | 26.03,26.04 26.03,61.6 R2.2 | 42.54,28.58 40.64,28.58 R7.2 | 42.54,28.58 42.54,38.73 IC8.14 | IC8.14 45.72,57.78 R9.1 | IC8.14 45.72,34.92 69.22,34.92 R12.2 | 42.54,28.58 46.35,28.58 46.35,24.13 45.72,24.13 IC7.14 | IC1.4 32.38,74.29 32.38,81.91 IC1.8 | IC9.14 90.81,30.48 97.16,30.48 97.16,55.88 103.51,64.13 103.51,66.68 R31.2 FB1.1 | C5.1 62.23,23.5 R11.2
  Bottom 0.406: IC4.5 12.06,50.16 10.79,50.16 10.79,61.6 | 10.79,61.6 IC3.5 12.06,64.13 26.03,64.13 | R2.2 26.03,61.6 26.03,64.13 | IC2.5 12.06,73.03 10.79,73.03 10.79,61.6 | IC7.14 45.72,24.13 46.99,24.13 46.99,27.3 62.23,27.3 R11.2 | R12.2 R13.2 76.2,31.12 87.63,31.12 87.63,28.58 IC9.14 | IC6.OUT 36.2,19.68 36.2,26.04 R7.2 R6.2 | IC1.4 28.57,64.13 26.03,64.13
  Bottom 1.016: IC6.OUT 26.03,20.95 C2.+
N$84
  Top 0.406: R43.2 139.06,73.66 139.06,59.69 C13.1
  Bottom 0.406: C13.1 141.61,59.69 141.61,56.52 159.38,56.52 159.38,60.32 R44.2 | R43.2 IC16.3
N$86
  Top 0.406: 159.38,47.62 C14.+ | 159.38,47.62 R47.1 | 159.38,47.62 159.38,67.31 148.59,67.31 148.59,62.87 IC17.2
  Bottom 0.406: R43.1 140.97,62.87 IC17.2
N$87
  Top 0.406: R47.2 155.58,57.78 155.58,34.92 159.38,34.92 C14.- 153.03,15.88 IC19.8
  Bottom 0.406: R47.2 155.58,57.78 155.58,60.32 IC17.6
N$89
  Bottom 0.406: IC17.3 148.59,60.32 148.59,61.6 162.56,61.6 R45.2 R46.1
N$94
  Top 0.406: IC18.6 147.96,39.37 147.96,18.41 IC19.6
  Bottom 0.406: IC18.6 IC18.5 147.32,41.91 147.32,46.99 IC18.3
N$95
  Top 0.406: IC19.10 IC19.9
  Bottom 0.406: IC19.10 147.96,20.95 147.96,22.23 142.24,22.23 142.24,20.95 134.62,20.95 134.62,46.35 139.06,46.35 SW5.4
N$97
  Bottom 0.406: 137.8,52.07 SW5.1 | IC11.9 104.78,64.77 104.78,67.31 137.8,67.31 137.8,52.07 | 137.8,52.07 SW5.2
N$98
  Bottom 0.406: R48.2 R50.3
N$99
  Bottom 0.406: R49.1 158.12,7.62 R50.1
N$100
  Bottom 0.406: R50.2 165.1,14.61 165.1,19.68 156.21,19.68 156.21,24.77 140.34,24.77 140.34,28.58 135.89,28.58 135.89,44.45 SW5.3

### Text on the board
Top: TOP
Bottom: BOTTOM
tPlace: FB1 | FB2 | 220k | 10nF | 10uF | 1M | 100k | 555 | 220k | 1N4001 | 1N4001 | 10uF NP | 555 | 7490 | 4017 | 4017 | 4017 | 4046 | 10k | 10k | 100k | 47k | 100nF | 10k | 10M | 4k7 | 100k | 560 | 100nF | 2k2 | 10pF | 100k | 741 | 4k7 | 2N3904 | 7490 | 4k7 | 100k | 318 | 2k2 | 4k7 | 1k | 27k | 1N4001 | 22k | 10k | 4001 | TP-2 | 470 | 10M | 4k7 | 7490 | 1uF NP | 10k | 2k2 | 4001 | 100k | +12V | 1nF | 2k2 | 2N3904 | 47k | 1N4148 | 74122 | 1k | 10k | 1N4001 | 1k | 1N4003 | 1N4003 | 2N3906 | 4k7 | 470 | 7404 | 10k | 10k | 22k | 330nF | 10uF NP | 10k | Tony Woodside - http://www.GlobalKast.com | 10pF | 1uF | 470 | Stanley A. Meyer Voltage Intensifier Circuit | 1k | 10k | 7408 | 4016/4066 | 7402 | 470 | 330uF | 10nF | 7805 | 2N3904 | 470 | TIP120 | 50k | 2N3906 | 2N3904 | 1k | 330uF | TP-1 | 470 | 10k | 7812 | GND | +12V | P- | P+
